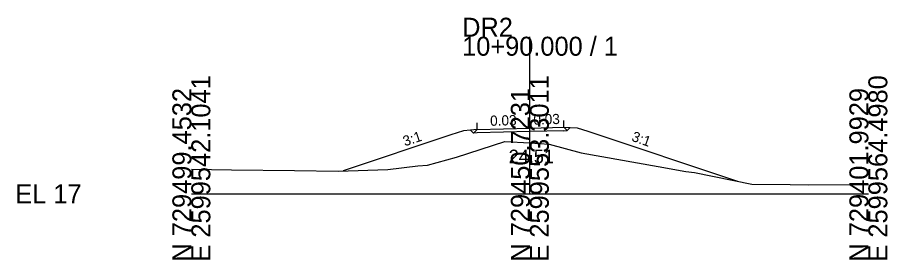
# Model space of a CAD drawing. Extents: x -26 to 1162, y -10 to 9515.
# Drawn here: x -25.7 to 102.8, y 4490.3 to 4526 of the extents above; entities that cross this region are included whole.
import ezdxf

# ---------------------------------------------------------------- set-up
doc = ezdxf.new("R2010")
doc.units = 0
for name, color, linetype in [('Exist Cross Section Cell', 7, 'Continuous'), ('Exist XS Center Line Elevation Label', 7, 'Continuous'), ('Exist XS Ground Line', 7, 'Continuous'), ('Prop XS Dump Level', 7, 'Continuous'), ('Prop XS EOT Tick Mark', 7, 'Continuous'), ('Prop XS Finish Grade', 7, 'Continuous'), ('Prop XS Finish Grade Earthwork', 7, 'Continuous'), ('Prop XS Finish Grade Pavement', 7, 'Continuous'), ('Prop XS Pvmt Edge Slope', 7, 'Continuous'), ('Prop XS SE Text', 7, 'Continuous'), ('Prop XS Side Slope Text', 7, 'Continuous'), ('Prop XS Subgrade Earthwork', 7, 'Continuous')]:
    doc.layers.add(name, color=color, linetype=linetype)

msp = doc.modelspace()

# ---------------------------------------------------------------- linework, layer by layer
at = {"layer": 'Exist Cross Section Cell'}
for p, q in [((50, 4500), (50, 4523.16)), ((0, 4500), (50, 4500)), ((50, 4500), (100, 4500))]:
    msp.add_line(p, q, dxfattribs=at)
at = {"layer": 'Exist XS Ground Line'}
msp.add_lwpolyline([(0, 4503.61), (5.92, 4503.53), (15.22, 4503.44), (21.69, 4503.36), (29.02, 4503.6), (33.45, 4504.11), (34.88, 4504.2), (39.17, 4505.42), (46.32, 4507.72), (50, 4507.51), (52.86, 4507.34), (57.56, 4506.06), (68.95, 4504.05), (73.02, 4503.3), (74.33, 4503.15), (82.81, 4501.42), (88.44, 4501.38), (91.2, 4501.31), (100, 4501.38)], dxfattribs=at)
at = {"layer": 'Prop XS Dump Level'}
for p, q in [((42.2, 4509.47), (50, 4509.68)), ((50, 4509.68), (55, 4509.81))]:
    msp.add_line(p, q, dxfattribs=at)
at = {"layer": 'Prop XS EOT Tick Mark'}
for p, q in [((42.2, 4509.47), (42.2, 4510.47)), ((55, 4509.81), (55, 4510.81))]:
    msp.add_line(p, q, dxfattribs=at)
at = {"layer": 'Prop XS Finish Grade'}
for p, q in [((42.2, 4509.47), (41.24, 4509.39)), ((55, 4509.81), (55.95, 4509.78))]:
    msp.add_line(p, q, dxfattribs=at)
at = {"layer": 'Prop XS Finish Grade Earthwork'}
for p, q in [((40.19, 4509.31), (38.33, 4508.69)), ((41.24, 4509.39), (40.19, 4509.31)), ((55.95, 4509.78), (57, 4509.75)), ((57, 4509.75), (58.57, 4509.23)), ((58.57, 4509.23), (80.68, 4501.86)), ((38.33, 4508.69), (22.42, 4503.39))]:
    msp.add_line(p, q, dxfattribs=at)
at = {"layer": 'Prop XS Finish Grade Pavement'}
for p, q in [((42.2, 4509.47), (50, 4509.68)), ((50, 4509.68), (55, 4509.81))]:
    msp.add_line(p, q, dxfattribs=at)
at = {"layer": 'Prop XS Pvmt Edge Slope'}
for p, q in [((41.68, 4508.95), (41.24, 4509.39)), ((42.2, 4509.47), (41.68, 4508.95)), ((55, 4509.81), (55.49, 4509.33)), ((55.49, 4509.33), (55.95, 4509.78))]:
    msp.add_line(p, q, dxfattribs=at)
at = {"layer": 'Prop XS Subgrade Earthwork'}
for p, q in [((41.68, 4508.95), (41.24, 4509.39)), ((42.2, 4508.97), (41.68, 4508.95)), ((50, 4509.18), (42.2, 4508.97)), ((55, 4509.31), (50, 4509.18)), ((55, 4509.31), (55.49, 4509.33)), ((55.49, 4509.33), (55.95, 4509.78))]:
    msp.add_line(p, q, dxfattribs=at)

# ---------------------------------------------------------------- texts
at = {"layer": 'Exist Cross Section Cell'}
for s, p in [('DR2', (40, 4523.16)), ('10+90.000 / 1', (40, 4520.36)), ('EL 17', (-26, 4498.6))]:
    msp.add_text(s, height=2.8, dxfattribs=at).set_placement(p)
for s, p in [('E 2599542.1041', (2.8, 4490)), ('E 2599553.3011', (52.8, 4490)), ('E 2599564.4980', (102.8, 4490)), ('N 729499.4532', (0, 4490)), ('N 729450.7231', (50, 4490)), ('N 729401.9929', (100, 4490))]:
    msp.add_text(s, height=2.8, rotation=90, dxfattribs=at).set_placement(p)
at = {"layer": 'Exist XS Center Line Elevation Label'}
msp.add_text('24.51', height=2, dxfattribs=at).set_placement((46.87, 4504.51))
at = {"layer": 'Prop XS Dump Level'}
for p in [(40.19, 4509.27), (57, 4509.71)]:
    msp.add_text('Case1', height=0.04, dxfattribs=at).set_placement(p)
at = {"layer": 'Prop XS SE Text'}
for p in [(44.15, 4510.02), (50.54, 4510.19)]:
    msp.add_text('0.03', height=1.5, rotation=1.5539, dxfattribs=at).set_placement(p)
at = {"layer": 'Prop XS Side Slope Text'}
for rotation, p in [(18.1082, (31.53, 4506.99)), (340.3993, (64.92, 4507.85))]:
    msp.add_text('3:1', height=1.5, rotation=rotation, dxfattribs=at).set_placement(p)

doc.saveas('drawing.dxf')
